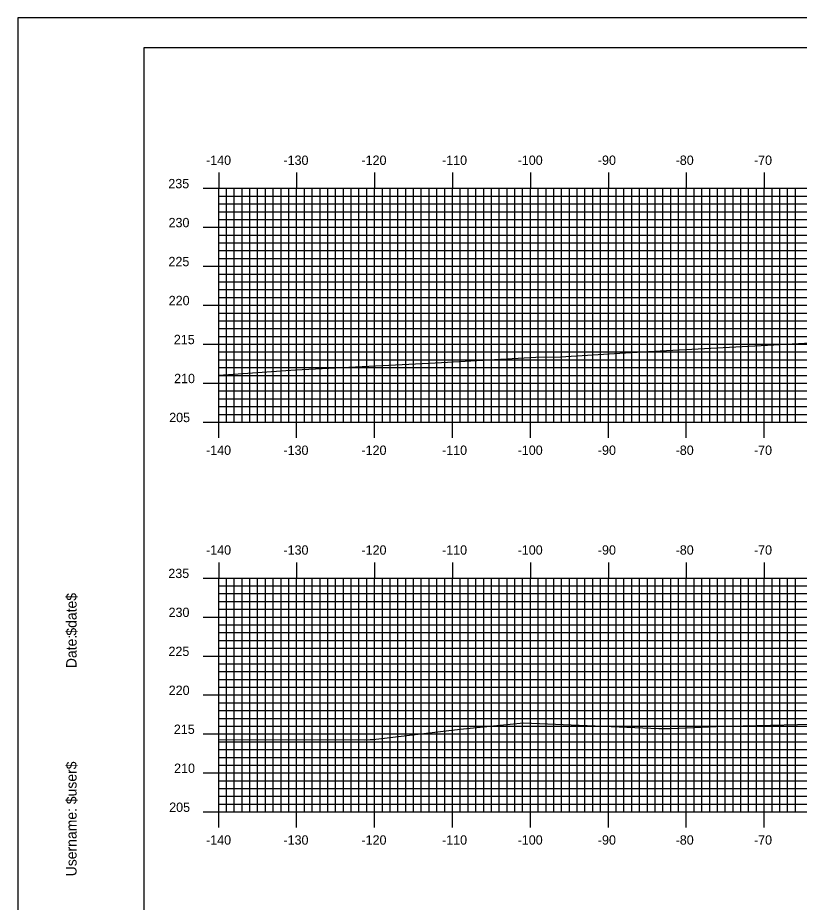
# Model space of a CAD drawing. Extents: x 850955 to 851298, y 364785 to 365005.
# Drawn here: x 850954.9 to 851055.2, y 364891.6 to 365005.1 of the extents above; entities that cross this region are included whole.
import ezdxf

# ---------------------------------------------------------------- set-up
doc = ezdxf.new("R2010")
doc.units = 0
for name, color, linetype in [('BORDER', 7, 'Continuous'), ('H_V ANNOTATION', 7, 'Continuous'), ('MAJOR', 7, 'Continuous'), ('MINOR', 7, 'Continuous'), ('PLOT BOUNDARY', 7, 'Continuous'), ('S_Roadway_Centerline', 7, 'Continuous')]:
    doc.layers.add(name, color=color, linetype=linetype)

msp = doc.modelspace()

# ---------------------------------------------------------------- linework, layer by layer
at = {"layer": 'BORDER'}
msp.add_lwpolyline([(850971.08, 364791.23), (851291.08, 364791.23), (851291.08, 365001.23), (850971.08, 365001.23)], close=True, dxfattribs=at)
at = {"layer": 'MAJOR'}
for p, q in [((850980.68, 364985.24), (850980.68, 364983.23)), ((850990.68, 364985.24), (850990.68, 364983.23)), ((851000.68, 364985.24), (851000.68, 364983.23)), ((851010.68, 364985.24), (851010.68, 364983.23)), ((851020.68, 364985.24), (851020.68, 364983.23)), ((851030.68, 364985.24), (851030.68, 364983.23)), ((851040.68, 364985.24), (851040.68, 364983.23)), ((851050.68, 364985.24), (851050.68, 364983.23)), ((850978.67, 364983.23), (850980.68, 364983.23)), ((850980.68, 364983.23), (851260.68, 364983.23)), ((850980.68, 364953.23), (850980.68, 364983.23)), ((850980.68, 364953.23), (850980.68, 364983.23)), ((850980.68, 364983.23), (851260.68, 364983.23)), ((850990.68, 364953.23), (850990.68, 364983.23)), ((851000.68, 364953.23), (851000.68, 364983.23)), ((851010.68, 364953.23), (851010.68, 364983.23)), ((851020.68, 364953.23), (851020.68, 364983.23)), ((851030.68, 364953.23), (851030.68, 364983.23)), ((851040.68, 364953.23), (851040.68, 364983.23)), ((851050.68, 364953.23), (851050.68, 364983.23)), ((850978.67, 364978.23), (850980.68, 364978.23)), ((850980.68, 364978.23), (851260.68, 364978.23)), ((850978.67, 364973.23), (850980.68, 364973.23)), ((850980.68, 364973.23), (851260.68, 364973.23)), ((850978.67, 364968.23), (850980.68, 364968.23)), ((850980.68, 364968.23), (851260.68, 364968.23)), ((850978.67, 364963.23), (850980.68, 364963.23)), ((850980.68, 364963.23), (851260.68, 364963.23)), ((850978.67, 364958.23), (850980.68, 364958.23)), ((850980.68, 364958.23), (851260.68, 364958.23)), ((850978.67, 364953.23), (850980.68, 364953.23)), ((850980.68, 364953.23), (851260.68, 364953.23)), ((850980.68, 364953.23), (851260.68, 364953.23)), ((850980.68, 364951.23), (850980.68, 364953.23)), ((850990.68, 364951.23), (850990.68, 364953.23)), ((851000.68, 364951.23), (851000.68, 364953.23)), ((851010.68, 364951.23), (851010.68, 364953.23)), ((851020.68, 364951.23), (851020.68, 364953.23)), ((851030.68, 364951.23), (851030.68, 364953.23)), ((851040.68, 364951.23), (851040.68, 364953.23)), ((851050.68, 364951.23), (851050.68, 364953.23)), ((850980.68, 364935.24), (850980.68, 364933.23)), ((850990.68, 364935.24), (850990.68, 364933.23)), ((851000.68, 364935.24), (851000.68, 364933.23)), ((851010.68, 364935.24), (851010.68, 364933.23)), ((851020.68, 364935.24), (851020.68, 364933.23)), ((851030.68, 364935.24), (851030.68, 364933.23)), ((851040.68, 364935.24), (851040.68, 364933.23)), ((851050.68, 364935.24), (851050.68, 364933.23)), ((850978.67, 364933.23), (850980.68, 364933.23)), ((850980.68, 364933.23), (851260.68, 364933.23)), ((850980.68, 364903.23), (850980.68, 364933.23)), ((850980.68, 364903.23), (850980.68, 364933.23)), ((850980.68, 364933.23), (851260.68, 364933.23)), ((850990.68, 364903.23), (850990.68, 364933.23)), ((851000.68, 364903.23), (851000.68, 364933.23)), ((851010.68, 364903.23), (851010.68, 364933.23)), ((851020.68, 364903.23), (851020.68, 364933.23)), ((851030.68, 364903.23), (851030.68, 364933.23)), ((851040.68, 364903.23), (851040.68, 364933.23)), ((851050.68, 364903.23), (851050.68, 364933.23)), ((850978.67, 364928.23), (850980.68, 364928.23)), ((850980.68, 364928.23), (851260.68, 364928.23)), ((850978.67, 364923.23), (850980.68, 364923.23)), ((850980.68, 364923.23), (851260.68, 364923.23)), ((850978.67, 364918.23), (850980.68, 364918.23)), ((850980.68, 364918.23), (851260.68, 364918.23)), ((850978.67, 364913.23), (850980.68, 364913.23)), ((850980.68, 364913.23), (851260.68, 364913.23)), ((850978.67, 364908.23), (850980.68, 364908.23)), ((850980.68, 364908.23), (851260.68, 364908.23)), ((850978.67, 364903.23), (850980.68, 364903.23)), ((850980.68, 364903.23), (851260.68, 364903.23)), ((850980.68, 364903.23), (851260.68, 364903.23)), ((850980.68, 364901.23), (850980.68, 364903.23)), ((850990.68, 364901.23), (850990.68, 364903.23)), ((851000.68, 364901.23), (851000.68, 364903.23)), ((851010.68, 364901.23), (851010.68, 364903.23)), ((851020.68, 364901.23), (851020.68, 364903.23)), ((851030.68, 364901.23), (851030.68, 364903.23)), ((851040.68, 364901.23), (851040.68, 364903.23)), ((851050.68, 364901.23), (851050.68, 364903.23))]:
    msp.add_line(p, q, dxfattribs=at)
at = {"layer": 'MINOR'}
for p, q in [((850981.68, 364953.23), (850981.68, 364983.23)), ((850982.68, 364953.23), (850982.68, 364983.23)), ((850983.68, 364953.23), (850983.68, 364983.23)), ((850984.68, 364953.23), (850984.68, 364983.23)), ((850985.68, 364953.23), (850985.68, 364983.23)), ((850986.68, 364953.23), (850986.68, 364983.23)), ((850987.68, 364953.23), (850987.68, 364983.23)), ((850988.68, 364953.23), (850988.68, 364983.23)), ((850989.68, 364953.23), (850989.68, 364983.23)), ((850991.68, 364953.23), (850991.68, 364983.23)), ((850992.68, 364953.23), (850992.68, 364983.23)), ((850993.68, 364953.23), (850993.68, 364983.23)), ((850994.68, 364953.23), (850994.68, 364983.23)), ((850995.68, 364953.23), (850995.68, 364983.23)), ((850996.68, 364953.23), (850996.68, 364983.23)), ((850997.68, 364953.23), (850997.68, 364983.23)), ((850998.68, 364953.23), (850998.68, 364983.23)), ((850999.68, 364953.23), (850999.68, 364983.23)), ((851001.68, 364953.23), (851001.68, 364983.23)), ((851002.68, 364953.23), (851002.68, 364983.23)), ((851003.68, 364953.23), (851003.68, 364983.23)), ((851004.68, 364953.23), (851004.68, 364983.23)), ((851005.68, 364953.23), (851005.68, 364983.23)), ((851006.68, 364953.23), (851006.68, 364983.23)), ((851007.68, 364953.23), (851007.68, 364983.23)), ((851008.68, 364953.23), (851008.68, 364983.23)), ((851009.68, 364953.23), (851009.68, 364983.23)), ((851011.68, 364953.23), (851011.68, 364983.23)), ((851012.68, 364953.23), (851012.68, 364983.23)), ((851013.68, 364953.23), (851013.68, 364983.23)), ((851014.68, 364953.23), (851014.68, 364983.23)), ((851015.68, 364953.23), (851015.68, 364983.23)), ((851016.68, 364953.23), (851016.68, 364983.23)), ((851017.68, 364953.23), (851017.68, 364983.23)), ((851018.68, 364953.23), (851018.68, 364983.23)), ((851019.68, 364953.23), (851019.68, 364983.23)), ((851021.68, 364953.23), (851021.68, 364983.23)), ((851022.68, 364953.23), (851022.68, 364983.23)), ((851023.68, 364953.23), (851023.68, 364983.23)), ((851024.68, 364953.23), (851024.68, 364983.23)), ((851025.68, 364953.23), (851025.68, 364983.23)), ((851026.68, 364953.23), (851026.68, 364983.23)), ((851027.68, 364953.23), (851027.68, 364983.23)), ((851028.68, 364953.23), (851028.68, 364983.23)), ((851029.68, 364953.23), (851029.68, 364983.23)), ((851031.68, 364953.23), (851031.68, 364983.23)), ((851032.68, 364953.23), (851032.68, 364983.23)), ((851033.68, 364953.23), (851033.68, 364983.23)), ((851034.68, 364953.23), (851034.68, 364983.23)), ((851035.68, 364953.23), (851035.68, 364983.23)), ((851036.68, 364953.23), (851036.68, 364983.23)), ((851037.68, 364953.23), (851037.68, 364983.23)), ((851038.68, 364953.23), (851038.68, 364983.23)), ((851039.68, 364953.23), (851039.68, 364983.23)), ((851041.68, 364953.23), (851041.68, 364983.23)), ((851042.68, 364953.23), (851042.68, 364983.23)), ((851043.68, 364953.23), (851043.68, 364983.23)), ((851044.68, 364953.23), (851044.68, 364983.23)), ((851045.68, 364953.23), (851045.68, 364983.23)), ((851046.68, 364953.23), (851046.68, 364983.23)), ((851047.68, 364953.23), (851047.68, 364983.23)), ((851048.68, 364953.23), (851048.68, 364983.23)), ((851049.68, 364953.23), (851049.68, 364983.23)), ((851051.68, 364953.23), (851051.68, 364983.23)), ((851052.68, 364953.23), (851052.68, 364983.23)), ((851053.68, 364953.23), (851053.68, 364983.23)), ((851054.68, 364953.23), (851054.68, 364983.23)), ((850980.68, 364982.23), (851260.68, 364982.23)), ((850980.68, 364982.23), (850982.68, 364982.23)), ((850980.68, 364981.23), (851260.68, 364981.23)), ((850980.68, 364981.23), (850982.68, 364981.23)), ((850980.68, 364980.23), (851260.68, 364980.23)), ((850980.68, 364980.23), (850982.68, 364980.23)), ((850980.68, 364979.23), (851260.68, 364979.23)), ((850980.68, 364979.23), (850982.68, 364979.23)), ((850980.68, 364977.23), (851260.68, 364977.23)), ((850980.68, 364977.23), (850982.68, 364977.23)), ((850980.68, 364976.23), (851260.68, 364976.23)), ((850980.68, 364976.23), (850982.68, 364976.23)), ((850980.68, 364975.23), (851260.68, 364975.23)), ((850980.68, 364975.23), (850982.68, 364975.23)), ((850980.68, 364974.23), (851260.68, 364974.23)), ((850980.68, 364974.23), (850982.68, 364974.23)), ((850980.68, 364972.23), (851260.68, 364972.23)), ((850980.68, 364972.23), (850982.68, 364972.23)), ((850980.68, 364971.23), (851260.68, 364971.23)), ((850980.68, 364971.23), (850982.68, 364971.23)), ((850980.68, 364970.23), (851260.68, 364970.23)), ((850980.68, 364970.23), (850982.68, 364970.23)), ((850980.68, 364969.23), (851260.68, 364969.23)), ((850980.68, 364969.23), (850982.68, 364969.23)), ((850980.68, 364967.23), (851260.68, 364967.23)), ((850980.68, 364967.23), (850982.68, 364967.23)), ((850980.68, 364966.23), (851260.68, 364966.23)), ((850980.68, 364966.23), (850982.68, 364966.23)), ((850980.68, 364965.23), (851260.68, 364965.23)), ((850980.68, 364965.23), (850982.68, 364965.23)), ((850980.68, 364964.23), (851260.68, 364964.23)), ((850980.68, 364964.23), (850982.68, 364964.23)), ((850980.68, 364962.23), (851260.68, 364962.23)), ((850980.68, 364962.23), (850982.68, 364962.23)), ((850980.68, 364961.23), (851260.68, 364961.23)), ((850980.68, 364961.23), (850982.68, 364961.23)), ((850980.68, 364960.23), (851260.68, 364960.23)), ((850980.68, 364960.23), (850982.68, 364960.23)), ((850980.68, 364959.23), (851260.68, 364959.23)), ((850980.68, 364959.23), (850982.68, 364959.23)), ((850980.68, 364957.23), (851260.68, 364957.23)), ((850980.68, 364957.23), (850982.68, 364957.23)), ((850980.68, 364956.23), (851260.68, 364956.23)), ((850980.68, 364956.23), (850982.68, 364956.23)), ((850980.68, 364955.23), (851260.68, 364955.23)), ((850980.68, 364955.23), (850982.68, 364955.23)), ((850980.68, 364954.23), (851260.68, 364954.23)), ((850980.68, 364954.23), (850982.68, 364954.23)), ((850981.68, 364903.23), (850981.68, 364933.23)), ((850982.68, 364903.23), (850982.68, 364933.23)), ((850983.68, 364903.23), (850983.68, 364933.23)), ((850984.68, 364903.23), (850984.68, 364933.23)), ((850985.68, 364903.23), (850985.68, 364933.23)), ((850986.68, 364903.23), (850986.68, 364933.23)), ((850987.68, 364903.23), (850987.68, 364933.23)), ((850988.68, 364903.23), (850988.68, 364933.23)), ((850989.68, 364903.23), (850989.68, 364933.23)), ((850991.68, 364903.23), (850991.68, 364933.23)), ((850992.68, 364903.23), (850992.68, 364933.23)), ((850993.68, 364903.23), (850993.68, 364933.23)), ((850994.68, 364903.23), (850994.68, 364933.23)), ((850995.68, 364903.23), (850995.68, 364933.23)), ((850996.68, 364903.23), (850996.68, 364933.23)), ((850997.68, 364903.23), (850997.68, 364933.23)), ((850998.68, 364903.23), (850998.68, 364933.23)), ((850999.68, 364903.23), (850999.68, 364933.23)), ((851001.68, 364903.23), (851001.68, 364933.23)), ((851002.68, 364903.23), (851002.68, 364933.23)), ((851003.68, 364903.23), (851003.68, 364933.23)), ((851004.68, 364903.23), (851004.68, 364933.23)), ((851005.68, 364903.23), (851005.68, 364933.23)), ((851006.68, 364903.23), (851006.68, 364933.23)), ((851007.68, 364903.23), (851007.68, 364933.23)), ((851008.68, 364903.23), (851008.68, 364933.23)), ((851009.68, 364903.23), (851009.68, 364933.23)), ((851011.68, 364903.23), (851011.68, 364933.23)), ((851012.68, 364903.23), (851012.68, 364933.23)), ((851013.68, 364903.23), (851013.68, 364933.23)), ((851014.68, 364903.23), (851014.68, 364933.23)), ((851015.68, 364903.23), (851015.68, 364933.23)), ((851016.68, 364903.23), (851016.68, 364933.23)), ((851017.68, 364903.23), (851017.68, 364933.23)), ((851018.68, 364903.23), (851018.68, 364933.23)), ((851019.68, 364903.23), (851019.68, 364933.23)), ((851021.68, 364903.23), (851021.68, 364933.23)), ((851022.68, 364903.23), (851022.68, 364933.23)), ((851023.68, 364903.23), (851023.68, 364933.23)), ((851024.68, 364903.23), (851024.68, 364933.23)), ((851025.68, 364903.23), (851025.68, 364933.23)), ((851026.68, 364903.23), (851026.68, 364933.23)), ((851027.68, 364903.23), (851027.68, 364933.23)), ((851028.68, 364903.23), (851028.68, 364933.23)), ((851029.68, 364903.23), (851029.68, 364933.23)), ((851031.68, 364903.23), (851031.68, 364933.23)), ((851032.68, 364903.23), (851032.68, 364933.23)), ((851033.68, 364903.23), (851033.68, 364933.23)), ((851034.68, 364903.23), (851034.68, 364933.23)), ((851035.68, 364903.23), (851035.68, 364933.23)), ((851036.68, 364903.23), (851036.68, 364933.23)), ((851037.68, 364903.23), (851037.68, 364933.23)), ((851038.68, 364903.23), (851038.68, 364933.23)), ((851039.68, 364903.23), (851039.68, 364933.23)), ((851041.68, 364903.23), (851041.68, 364933.23)), ((851042.68, 364903.23), (851042.68, 364933.23)), ((851043.68, 364903.23), (851043.68, 364933.23)), ((851044.68, 364903.23), (851044.68, 364933.23)), ((851045.68, 364903.23), (851045.68, 364933.23)), ((851046.68, 364903.23), (851046.68, 364933.23)), ((851047.68, 364903.23), (851047.68, 364933.23)), ((851048.68, 364903.23), (851048.68, 364933.23)), ((851049.68, 364903.23), (851049.68, 364933.23)), ((851051.68, 364903.23), (851051.68, 364933.23)), ((851052.68, 364903.23), (851052.68, 364933.23)), ((851053.68, 364903.23), (851053.68, 364933.23)), ((851054.68, 364903.23), (851054.68, 364933.23)), ((850980.68, 364932.23), (851260.68, 364932.23)), ((850980.68, 364932.23), (850982.68, 364932.23)), ((850980.68, 364931.23), (851260.68, 364931.23)), ((850980.68, 364931.23), (850982.68, 364931.23)), ((850980.68, 364930.23), (851260.68, 364930.23)), ((850980.68, 364930.23), (850982.68, 364930.23)), ((850980.68, 364929.23), (851260.68, 364929.23)), ((850980.68, 364929.23), (850982.68, 364929.23)), ((850980.68, 364927.23), (851260.68, 364927.23)), ((850980.68, 364927.23), (850982.68, 364927.23)), ((850980.68, 364926.23), (851260.68, 364926.23)), ((850980.68, 364926.23), (850982.68, 364926.23)), ((850980.68, 364925.23), (851260.68, 364925.23)), ((850980.68, 364925.23), (850982.68, 364925.23)), ((850980.68, 364924.23), (851260.68, 364924.23)), ((850980.68, 364924.23), (850982.68, 364924.23)), ((850980.68, 364922.23), (851260.68, 364922.23)), ((850980.68, 364922.23), (850982.68, 364922.23)), ((850980.68, 364921.23), (851260.68, 364921.23)), ((850980.68, 364921.23), (850982.68, 364921.23)), ((850980.68, 364920.23), (851260.68, 364920.23)), ((850980.68, 364920.23), (850982.68, 364920.23)), ((850980.68, 364919.23), (851260.68, 364919.23)), ((850980.68, 364919.23), (850982.68, 364919.23)), ((850980.68, 364917.23), (851260.68, 364917.23)), ((850980.68, 364917.23), (850982.68, 364917.23)), ((850980.68, 364916.23), (851260.68, 364916.23)), ((850980.68, 364916.23), (850982.68, 364916.23)), ((850980.68, 364915.23), (851260.68, 364915.23)), ((850980.68, 364915.23), (850982.68, 364915.23)), ((850980.68, 364914.23), (851260.68, 364914.23)), ((850980.68, 364914.23), (850982.68, 364914.23)), ((850980.68, 364912.23), (851260.68, 364912.23)), ((850980.68, 364912.23), (850982.68, 364912.23)), ((850980.68, 364911.23), (851260.68, 364911.23)), ((850980.68, 364911.23), (850982.68, 364911.23)), ((850980.68, 364910.23), (851260.68, 364910.23)), ((850980.68, 364910.23), (850982.68, 364910.23)), ((850980.68, 364909.23), (851260.68, 364909.23)), ((850980.68, 364909.23), (850982.68, 364909.23)), ((850980.68, 364907.23), (851260.68, 364907.23)), ((850980.68, 364907.23), (850982.68, 364907.23)), ((850980.68, 364906.23), (851260.68, 364906.23)), ((850980.68, 364906.23), (850982.68, 364906.23)), ((850980.68, 364905.23), (851260.68, 364905.23)), ((850980.68, 364905.23), (850982.68, 364905.23)), ((850980.68, 364904.23), (851260.68, 364904.23)), ((850980.68, 364904.23), (850982.68, 364904.23))]:
    msp.add_line(p, q, dxfattribs=at)
at = {"layer": 'PLOT BOUNDARY'}
msp.add_lwpolyline([(850954.89, 364785.11), (851294.89, 364785.11), (851294.89, 365005.11), (850954.89, 365005.11)], close=True, dxfattribs=at)
at = {"layer": 'S_Roadway_Centerline'}
for points in [[(850980.68, 364959.26), (850985.01, 364959.55), (850990.54, 364959.96), (851006.8, 364960.76), (851009.26, 364960.89), (851021.38, 364961.58), (851024.55, 364961.6), (851032.17, 364962.06), (851037.34, 364962.36), (851051.92, 364963.14), (851067.63, 364963.99)], [(850980.68, 364912.46), (850982.73, 364912.53), (850999.38, 364912.47), (851000.12, 364912.52), (851000.51, 364912.52), (851011.65, 364913.85), (851019.78, 364914.66), (851037.16, 364913.94), (851038.72, 364913.94), (851044.48, 364914.18), (851061.95, 364914.63)]]:
    msp.add_lwpolyline(points, dxfattribs=at)

# ---------------------------------------------------------------- texts
at = {"layer": 'BORDER'}
for s, p in [('$date$', (850962.45, 364925.84)), ('Date:', (850962.45, 364921.67)), ('$user$', (850962.45, 364904.22)), ('Username:', (850962.45, 364894.97))]:
    msp.add_text(s, height=1.339, rotation=90, dxfattribs=at).set_placement(p)
at = {"layer": 'H_V ANNOTATION'}
for s, p in [('-140', (850979.06, 364986.23)), ('-130', (850988.99, 364986.23)), ('-120', (850999, 364986.23)), ('-110', (851009.34, 364986.23)), ('-100', (851019.04, 364986.23)), ('-90', (851029.33, 364986.23)), ('-80', (851039.31, 364986.23)), ('-70', (851049.36, 364986.23)), ('235', (850974.22, 364983.23)), ('230', (850974.25, 364978.23)), ('225', (850974.24, 364973.23)), ('220', (850974.27, 364968.23)), ('215', (850974.93, 364963.23)), ('210', (850974.96, 364958.23)), ('205', (850974.33, 364953.23)), ('-140', (850979.06, 364949.03)), ('-130', (850988.99, 364949.03)), ('-120', (850999, 364949.03)), ('-110', (851009.34, 364949.03)), ('-100', (851019.04, 364949.03)), ('-90', (851029.33, 364949.03)), ('-80', (851039.31, 364949.03)), ('-70', (851049.36, 364949.03)), ('-140', (850979.06, 364936.23)), ('-130', (850988.99, 364936.23)), ('-120', (850999, 364936.23)), ('-110', (851009.34, 364936.23)), ('-100', (851019.04, 364936.23)), ('-90', (851029.33, 364936.23)), ('-80', (851039.31, 364936.23)), ('-70', (851049.36, 364936.23)), ('235', (850974.22, 364933.23)), ('230', (850974.25, 364928.23)), ('225', (850974.24, 364923.23)), ('220', (850974.27, 364918.23)), ('215', (850974.93, 364913.23)), ('210', (850974.96, 364908.23)), ('205', (850974.33, 364903.23)), ('-140', (850979.06, 364899.03)), ('-130', (850988.99, 364899.03)), ('-120', (850999, 364899.03)), ('-110', (851009.34, 364899.03)), ('-100', (851019.04, 364899.03)), ('-90', (851029.33, 364899.03)), ('-80', (851039.31, 364899.03)), ('-70', (851049.36, 364899.03))]:
    msp.add_text(s, height=1.2, dxfattribs=at).set_placement(p)
at = {"layer": 'MAJOR'}
for p in [(850980.67, 364953.23), (850980.67, 364903.23)]:
    msp.add_text('-', height=0.012, dxfattribs=at).set_placement(p)

doc.saveas('drawing.dxf')
